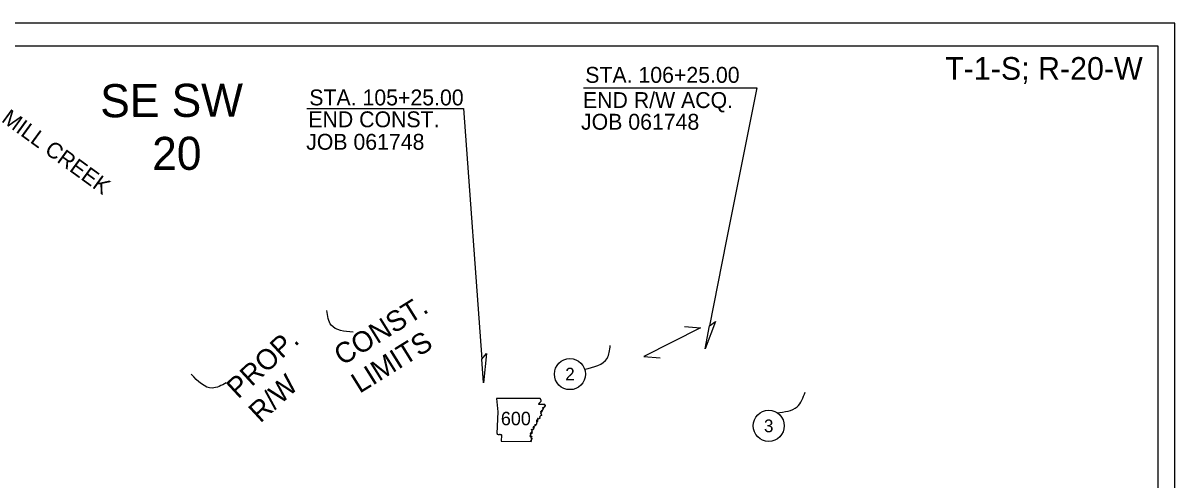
# Model space of a CAD drawing. Extents: x -3711 to 825, y -151 to 1050.
# Drawn here: x 318 to 825, y 324 to 525 of the extents above; entities that cross this region are included whole.
import ezdxf

# ---------------------------------------------------------------- set-up
doc = ezdxf.new("R2010")
doc.units = 0
for name, color, linetype in [('E_Const Align Station', 7, 'Continuous'), ('E_Label', 7, 'Continuous'), ('E_PL and Hook', 7, 'Continuous'), ('E_Quarter Calls', 7, 'Continuous'), ('E_Sheet Border', 7, 'Continuous'), ('E_Street Sub Info', 7, 'Continuous'), ('R_No Plot', 7, 'Continuous')]:
    doc.layers.add(name, color=color, linetype=linetype)

msp = doc.modelspace()

# ---------------------------------------------------------------- linework, layer by layer
at = {"layer": 'E_Const Align Station'}
for centre in [(558.77, 370.4), (646.23, 347.62)]:
    msp.add_circle(centre, 6.84, dxfattribs=at)
for points in [[(463.33, 388.82), (453.75, 391.96), (451.74, 398.41)], [(565.3, 372.55), (575.14, 377.35), (576.53, 383.03)], [(407.53, 366.59), (401.36, 364.24), (392.09, 370.35)], [(649.83, 353.42), (658.72, 356.01), (662.26, 362.51)]]:
    msp.add_spline(points, degree=3, dxfattribs=at)
at = {"layer": 'E_Label'}
for p, q in [((641.01, 496.52), (627.55, 428.93)), ((442.98, 487.4), (511.95, 487.4)), ((511.95, 487.4), (519.94, 376.98)), ((627.55, 428.93), (620.14, 391.73)), ((622.88, 393.54), (618.22, 381.5)), ((618.22, 381.5), (620.14, 391.73)), ((620.14, 391.73), (622.88, 393.54)), ((519.94, 376.98), (522.09, 379.46)), ((520.8, 366.62), (519.94, 376.98)), ((522.09, 379.46), (520.8, 366.62))]:
    msp.add_line(p, q, dxfattribs=at)
msp.add_lwpolyline([(564.71, 496.51), (564.7, 496.51), (641.01, 496.51)], dxfattribs=at)
at = {"layer": 'E_PL and Hook'}
for p, q in [((616.29, 390.74), (591.35, 378.16)), ((609.23, 391.38), (616.29, 390.74)), ((591.35, 378.16), (598.42, 377.52))]:
    msp.add_line(p, q, dxfattribs=at)
at = {"layer": 'E_Sheet Border'}
for p, q in [((27.5, 515), (817.5, 515)), ((817.5, 515), (817.5, 10))]:
    msp.add_line(p, q, dxfattribs=at)
msp.add_lwpolyline([(0, 0), (825, 0), (825, 525), (0, 525)], close=True, dxfattribs=at)
at = {"layer": 'E_Street Sub Info'}
for points in [[(526.38, 359.71), (527.01, 353.79), (526.63, 344.25), (526.63, 344.25), (526.68, 344.22), (526.73, 344.18), (526.75, 344.14), (526.76, 344.1), (526.73, 344.08), (526.73, 344.02), (526.78, 343.95), (526.86, 343.9), (526.88, 343.87), (526.9, 343.85), (526.95, 343.9), (527, 343.89), (527.01, 343.82), (526.98, 343.77), (527.02, 343.69), (527.09, 343.73), (527.13, 343.79), (527.22, 343.84), (527.28, 343.77), (527.31, 343.73), (527.38, 343.82), (527.41, 343.86), (527.47, 343.78), (527.48, 343.74), (527.59, 343.85), (527.64, 343.88), (527.7, 343.81), (527.71, 343.75), (527.81, 343.86), (527.85, 343.9), (527.91, 343.91), (528.04, 343.97), (528.07, 343.84), (528.15, 343.81), (528.23, 343.81), (528.28, 343.85), (528.39, 343.81), (528.47, 343.86), (528.54, 343.81), (528.63, 343.72), (528.66, 343.58), (528.53, 340.81), (541.65, 340.73), (541.8, 340.95), (541.42, 341.34), (541.88, 341.37), (541.97, 341.82), (542.12, 342.21), (541.86, 342.1), (541.71, 342.23), (541.63, 342.38), (541.81, 342.72), (541.99, 342.93), (541.94, 343.05), (541.8, 342.83), (541.47, 342.8), (541.45, 342.89), (541.71, 343.03), (541.77, 343.16), (541.66, 343.34), (541.56, 343.29), (541.49, 343.1), (541.38, 343.06), (541.29, 343.07), (541.29, 343.17), (541.42, 343.3), (541.43, 343.46), (541.25, 343.67), (541.45, 343.78), (541.61, 343.92), (541.59, 344.08), (541.38, 344.3), (541.36, 344.47), (541.6, 344.42), (541.79, 344.28), (541.97, 344.23), (542.12, 344.37), (542.13, 344.48), (541.95, 344.53), (541.78, 344.55), (541.69, 344.65), (541.66, 344.78), (541.66, 344.88), (541.76, 344.88), (541.86, 344.89), (541.97, 344.95), (542.06, 344.88), (542.16, 344.83), (542.27, 344.92), (542.29, 345), (542.14, 345.12), (542.07, 345.26), (542.07, 345.49), (542.14, 345.66), (542.13, 345.77), (542.02, 345.9), (541.93, 346.03)], [(546.09, 359.07), (546.01, 359.14), (545.9, 359.26), (545.86, 359.38), (545.8, 359.52), (545.74, 359.63), (540.3, 359.62), (536.6, 359.63), (529.64, 359.63), (526.4, 359.71)], [(545.45, 351.47), (545.41, 351.6), (545.56, 351.74), (545.73, 351.82), (545.81, 351.87), (545.85, 352.05), (545.89, 352.19), (546.06, 352.31), (546.19, 352.27), (546.3, 352.23), (546.36, 352.34), (546.31, 352.47), (546.29, 352.66), (546.29, 352.8), (546.27, 352.96), (546.15, 352.99), (545.93, 353.1), (545.92, 353.15), (546.01, 353.21), (546.12, 353.27), (546.16, 353.31), (546.16, 353.4), (546.18, 353.51), (546.26, 353.63), (546.25, 353.76), (546.14, 353.85), (546.08, 353.84), (546.05, 353.74), (546.01, 353.67), (545.9, 353.68), (545.87, 353.77), (545.92, 353.89), (546.02, 354.03), (546.11, 354.1), (546.25, 354.14), (546.29, 354), (546.3, 353.89), (546.38, 353.82), (546.49, 353.96), (546.5, 354.17), (546.46, 354.44), (546.47, 354.52), (546.6, 354.6), (546.73, 354.54), (546.84, 354.46), (546.9, 354.48), (546.86, 354.64), (546.79, 354.75), (546.85, 354.87), (547.04, 355), (547.15, 355.13), (547.13, 355.22), (546.88, 355.22), (546.76, 355.36), (546.79, 355.57), (546.87, 355.66), (547.06, 355.72), (547.28, 355.73), (547.42, 355.77), (547.48, 355.91), (547.54, 355.99), (547.75, 356), (547.84, 356.11), (547.84, 356.16), (547.78, 356.23), (547.64, 356.32), (547.56, 356.43), (547.65, 356.47), (547.85, 356.46), (548, 356.46), (548.04, 356.48), (548.04, 356.55), (547.95, 356.67), (547.83, 356.76), (547.74, 356.85), (547.7, 356.94), (547.7, 357.03), (544.94, 356.97), (544.98, 357.03), (545, 357.09), (545.01, 357.13), (545.04, 357.24), (545.08, 357.33), (545.14, 357.39), (545.2, 357.48), (545.25, 357.57), (545.39, 357.62), (545.44, 357.71), (545.46, 357.82), (545.49, 357.91), (545.61, 358.06), (545.73, 358.12), (545.82, 358.16), (545.89, 358.22), (545.94, 358.31), (546.03, 358.41), (546.11, 358.46), (546.13, 358.53), (546.11, 358.68), (546.12, 359.04), (546.09, 359.07)], [(541.91, 346.05), (541.92, 346.1), (541.98, 346.08), (542.08, 346.01), (542.18, 346), (542.24, 346.01), (542.36, 345.89), (542.4, 345.86), (542.48, 345.91), (542.52, 346.11), (542.46, 346.15), (542.59, 346.19), (542.73, 346.21), (542.81, 346.32), (542.85, 346.47), (542.75, 346.61), (542.56, 346.72), (542.52, 346.81), (542.59, 346.9), (542.78, 346.91), (542.91, 346.88), (543, 346.89), (543.12, 346.95), (543.1, 347.02), (543.06, 347.1), (542.96, 347.14), (542.82, 347.15), (542.67, 347.23), (542.57, 347.36), (542.66, 347.41), (542.83, 347.32), (542.92, 347.31), (543.02, 347.44), (543.11, 347.56), (543.19, 347.61), (543.38, 347.64), (543.47, 347.7), (543.44, 347.83), (543.37, 348.01), (543.42, 348.11), (543.51, 348.15), (543.56, 348.15), (543.67, 348.19), (543.69, 348.17), (543.72, 348.1), (543.67, 347.97), (543.8, 347.86), (543.84, 347.95), (543.82, 348.04), (543.82, 348.11), (543.93, 348.29), (544.18, 348.47), (544.19, 348.59), (544.15, 348.73), (544.2, 348.92), (544.32, 349.04), (544.34, 349.14), (544.26, 349.26), (544.19, 349.39), (544.16, 349.56), (544.18, 349.74), (544.21, 349.85), (544.28, 349.87), (544.32, 349.78), (544.33, 349.65), (544.38, 349.53), (544.47, 349.55), (544.58, 349.66), (544.63, 349.79), (544.63, 349.88), (544.5, 349.96), (544.35, 349.97), (544.23, 350.04), (544.24, 350.11), (544.29, 350.17), (544.31, 350.28), (544.29, 350.4), (544.36, 350.46), (544.43, 350.4), (544.44, 350.3), (544.43, 350.2), (544.5, 350.12), (544.59, 350.19), (544.62, 350.3), (544.62, 350.47), (544.63, 350.68), (544.54, 350.83), (544.57, 350.98), (544.75, 350.94), (544.88, 350.76), (545, 350.73), (545.17, 350.82), (545.31, 350.76), (545.36, 350.73), (545.34, 350.85), (545.5, 350.99), (545.55, 350.99), (545.64, 351.07), (545.63, 351.21), (545.55, 351.32), (545.45, 351.47)], [(541.93, 346.03), (541.97, 346.13)]]:
    msp.add_lwpolyline(points, dxfattribs=at)
at = {"layer": 'R_No Plot'}
msp.add_lwpolyline([(0, 0), (825, 0), (825, 525), (0, 525)], close=True, dxfattribs=at)

# ---------------------------------------------------------------- texts
at = {"layer": 'E_Const Align Station'}
for s, p in [('2', (556.7, 367.6)), ('3', (644.15, 344.82))]:
    msp.add_text(s, height=5.6, dxfattribs=at).set_placement(p)
at = {"layer": 'E_Label'}
for s, height, rotation, p in [('STA. 106+25.00', 7, 360, (565.51, 498.67)), ('STA. 105+25.00', 7, 360, (444.08, 488.73)), ('END R/W ACQ.', 7, 360, (564.5, 487.57)), ('MILL CREEK', 7, 323.97, (308.21, 481.84)), ('END CONST.', 7, 360, (443.65, 479.1)), ('JOB 061748', 7, 360, (563.64, 478.02)), ('JOB 061748', 7, 360, (442.7, 469.2)), ('CONST.', 9, 31.9315, (458.59, 373.92)), ('PROP. ', 9, 42.7273, (412.77, 359.16)), ('LIMITS', 9, 31.9315, (466.21, 361.7)), ('R/W', 9, 42.7273, (422.54, 348.58))]:
    msp.add_text(s, height=height, rotation=rotation, dxfattribs=at).set_placement(p)
at = {"layer": 'E_Quarter Calls'}
for s, p in [('SE SW', (352.12, 483.47)), ('20', (374.98, 460.26))]:
    msp.add_text(s, height=14.58, rotation=0.2962, dxfattribs=at).set_placement(p)
at = {"layer": 'E_Sheet Border'}
msp.add_text('T-1-S; R-20-W', height=10, dxfattribs=at).set_placement((723.88, 500))
at = {"layer": 'E_Street Sub Info'}
msp.add_text('600', height=5.912, dxfattribs=at).set_placement((528.38, 347.9))

doc.saveas('drawing.dxf')
